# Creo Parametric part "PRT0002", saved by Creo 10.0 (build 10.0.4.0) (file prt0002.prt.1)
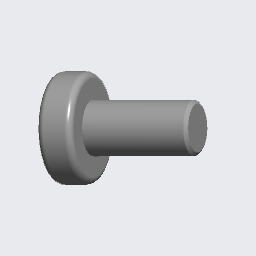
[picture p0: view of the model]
Units: millimeter Kilogram Sec (mmKs); MM, KILOGRAM, SECS

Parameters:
  MERGE_BASE_PART = "M3_SCREW"

Other named items: RIGHT, TOP, FRONT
